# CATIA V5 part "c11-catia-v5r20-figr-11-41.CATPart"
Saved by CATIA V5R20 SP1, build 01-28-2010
Part number: Part1
Bounding box of the stored display mesh (mm): x -59 to 59, y -60 to 210, z -30 to 39.8
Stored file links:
  D:\v5_r20\psrt_files_downloaded\c11\c11-catia-v5r20-figr-11-41.CATPart
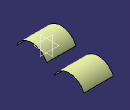
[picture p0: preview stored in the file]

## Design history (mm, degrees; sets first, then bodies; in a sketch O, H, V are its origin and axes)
AxisSystem1: origin (0, 0, 0), X (1, 0, 0), Y (0, 1, 0), Z (0, 0, 1)
AxisSystem2: origin (0, 150, -30), X (1, 0, 0), Y (0, 1, 0), Z (0, 0, 1)
Set1
  Extrude1: Element1 Sketch2, Lim1 59, Lim2 59, Direction yz-plane
  Sketch1 on yz-plane, origin (0, 0, 0), H (0, 1, 0), V (0, 0, 1)
    point P1 (150, -30)
  AxisToAxis1: ToTransfor Extrude1, AxisOrigin AxisSystem1, Axis AxisSystem2
Body1 (main body)
  Sketch2 on yz-plane, origin (0, 0, 0), H (0, 1, 0), V (0, 0, 1)
    arc A1 centre (0, -25) radius 65 from (-60, 0) to (60, 0) cw
    point P2 (-60, 0)
    point P3 (60, 0)
    coincidence: P2 H, P3 H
